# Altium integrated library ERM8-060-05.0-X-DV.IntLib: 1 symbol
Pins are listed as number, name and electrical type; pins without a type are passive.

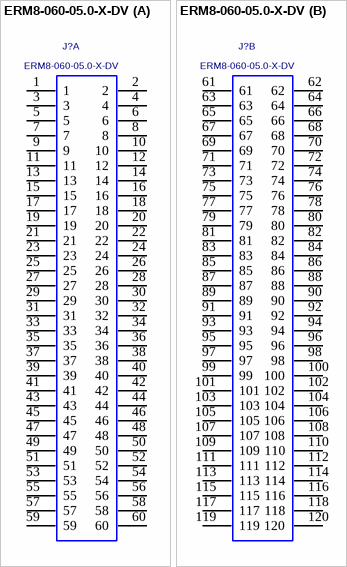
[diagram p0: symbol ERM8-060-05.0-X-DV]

## ERM8-060-05.0-X-DV
designator J?
0.8mm Edge Rate Terminal Assembly, Double Vertical Row, 60 Positions.; MANFACTURER: SAMTEC
footprint ERM8-060-05.0-X-DV (Footprint not found)
part A pins: 1, 2, 3, 4, 5, 6, 7, 8, 9, 10, 11, 12, 13, 14, 15, 16, 17, 18, 19, 20, 21, 22, 23, 24, 25, 26, 27, 28, 29, 30, 31, 32, 33, 34, 35, 36, 37, 38, 39, 40, 41, 42, 43, 44, 45, 46, 47, 48, 49, 50, 51, 52, 53, 54, 55, 56, 57, 58, 59, 60
part B pins: 61, 62, 63, 64, 65, 66, 67, 68, 69, 70, 71, 72, 73, 74, 75, 76, 77, 78, 79, 80, 81, 82, 83, 84, 85, 86, 87, 88, 89, 90, 91, 92, 93, 94, 95, 96, 97, 98, 99, 100, 101, 102, 103, 104, 105, 106, 107, 108, 109, 110, 111, 112, 113, 114, 115, 116, 117, 118, 119, 120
